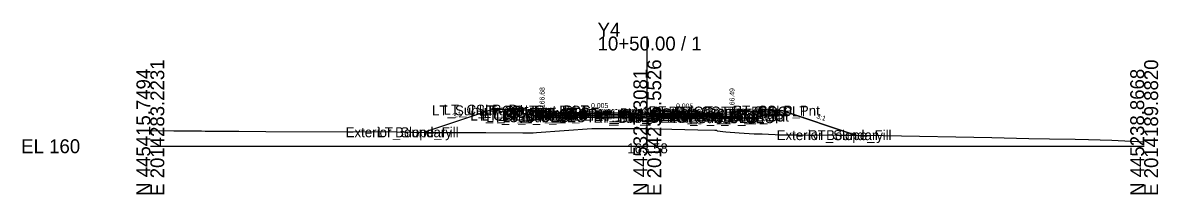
# Model space of a CAD drawing. Extents: x -26 to 203, y -10 to 4021.
# Drawn here: x -25.7 to 202.8, y 990.3 to 1024.9 of the extents above; entities that cross this region are included whole.
import ezdxf

# ---------------------------------------------------------------- set-up
doc = ezdxf.new("R2010")
doc.units = 0
for name, color, linetype in [('Default', 7, 'Continuous'), ('Exist Cross Section Cell', 7, 'Continuous'), ('Exist XS Center Line Elevation Label', 7, 'Continuous'), ('Exist XS Ground Line', 7, 'Continuous'), ('Prop CMT Conc Surface', 7, 'Continuous'), ('Prop CMT Concrete Structures', 7, 'Continuous'), ('Prop CMT Pvmt Course 1', 7, 'Continuous'), ('Prop CMT Pvmt Course 1 CG', 7, 'Continuous'), ('Prop CMT Pvmt Course 2', 7, 'Continuous'), ('Prop CMT Pvmt Course 3', 7, 'Continuous'), ('Prop CMT Pvmt Surface', 7, 'Continuous'), ('Prop CMT Slope Grass', 7, 'Continuous'), ('Prop CMT Subgrade Earthwork', 7, 'Continuous'), ('Prop XS Earthwork Shape', 7, 'Continuous'), ('Prop XS Hydro Elevations', 7, 'Continuous'), ('Prop XS SE Text', 7, 'Continuous'), ('Prop XS Side Slope Text', 7, 'Continuous'), ('Scratch_Level_0', 7, 'Continuous')]:
    doc.layers.add(name, color=color, linetype=linetype)

msp = doc.modelspace()

# ---------------------------------------------------------------- linework, layer by layer
at = {"layer": 'Exist Cross Section Cell'}
for p, q in [((100, 1000), (100, 1022.1)), ((0, 1000), (100, 1000)), ((100, 1000), (200, 1000))]:
    msp.add_line(p, q, dxfattribs=at)
at = {"layer": 'Exist XS Ground Line'}
msp.add_lwpolyline([(0, 1003.19), (4.69, 1003.1), (10.27, 1003.09), (11.05, 1003.06), (15.46, 1003.03), (17.82, 1003.04), (23.21, 1003), (41.56, 1002.89), (46.71, 1002.96), (55.46, 1002.8), (62.38, 1002.75), (67.52, 1002.77), (74.97, 1002.71), (77.03, 1002.69), (77.71, 1002.74), (88.86, 1003.57), (93.52, 1003.58), (99.73, 1003.59), (110.2, 1003.33), (113.59, 1003.22), (113.99, 1003.21), (114.05, 1003.09), (115.78, 1002.89), (118.52, 1002.67), (121.54, 1002.53), (121.94, 1002.51), (123.11, 1002.48), (126.99, 1002.27), (129.16, 1002.33), (130.4, 1002.3), (137.99, 1002.26), (140.42, 1002.26), (147.5, 1002.13), (151.18, 1002.07), (165.74, 1001.84), (169.37, 1001.76), (176.8, 1001.56), (180.95, 1001.49), (186.08, 1001.42), (188.79, 1001.38), (193.48, 1001.25), (200, 1000.87)], dxfattribs=at)
at = {"layer": 'Prop CMT Conc Surface'}
for points in [[(78.83, 1006.68), (78.83, 1007.18), (78.33, 1007.18)], [(80.83, 1006.75), (78.83, 1006.68)], [(115.05, 1006.58), (117.05, 1006.49)], [(117.05, 1006.49), (117.05, 1006.99), (117.55, 1006.99)]]:
    msp.add_lwpolyline(points, dxfattribs=at)
at = {"layer": 'Prop CMT Concrete Structures'}
for points in [[(80.83, 1006.75), (78.83, 1006.68), (78.83, 1007.18), (78.33, 1007.18)], [(78.33, 1007.18), (78.33, 1006.18), (80.83, 1006.16)], [(80.83, 1006.16), (80.83, 1006.75)], [(115.05, 1006.58), (117.05, 1006.49), (117.05, 1006.99), (117.55, 1006.99)], [(117.55, 1006.99), (117.55, 1005.98), (115.05, 1005.99)], [(115.05, 1005.99), (115.05, 1006.58)]]:
    msp.add_lwpolyline(points, dxfattribs=at)
at = {"layer": 'Prop CMT Pvmt Course 1'}
for points in [[(100, 1006.65), (80.83, 1006.75)], [(80.83, 1006.75), (80.83, 1006.5)], [(80.83, 1006.5), (100, 1006.4)], [(100, 1006.4), (100, 1006.65)], [(100, 1006.65), (115.05, 1006.58)], [(100, 1006.4), (100, 1006.65)], [(115.05, 1006.33), (100, 1006.4)], [(115.05, 1006.58), (115.05, 1006.33)]]:
    msp.add_lwpolyline(points, dxfattribs=at)
msp.add_lwpolyline([(100, 1006.4), (100, 1006.53), (100, 1006.53), (100, 1006.4)], close=True, dxfattribs=at)
msp.add_lwpolyline([(100, 1006.4), (100, 1006.53), (100, 1006.53), (100, 1006.4)], close=True, dxfattribs=at)
at = {"layer": 'Prop CMT Pvmt Course 1 CG'}
for points in [[(80.83, 1006.16), (77.83, 1006.18), (77.5, 1005.85)], [(77.5, 1005.85), (80.83, 1005.83)], [(80.83, 1005.83), (80.83, 1006.16)], [(115.05, 1005.99), (118.05, 1005.98), (118.38, 1005.64)], [(115.05, 1005.66), (115.05, 1005.99)], [(118.38, 1005.64), (115.05, 1005.66)]]:
    msp.add_lwpolyline(points, dxfattribs=at)
at = {"layer": 'Prop CMT Pvmt Course 2'}
for points in [[(100, 1006.4), (80.83, 1006.5)], [(80.83, 1006.5), (80.83, 1006.16)], [(80.83, 1006.16), (100, 1006.07)], [(100, 1006.07), (100, 1006.4)], [(100, 1006.07), (100, 1006.4)], [(100, 1006.4), (115.05, 1006.33)], [(115.05, 1005.99), (100, 1006.07)], [(115.05, 1006.33), (115.05, 1005.99)]]:
    msp.add_lwpolyline(points, dxfattribs=at)
at = {"layer": 'Prop CMT Pvmt Course 3'}
for points in [[(100, 1006.07), (80.83, 1006.16)], [(80.83, 1006.16), (80.83, 1005.83)], [(80.83, 1005.83), (100, 1005.73)], [(100, 1005.73), (100, 1006.07)], [(100, 1006.07), (115.05, 1005.99)], [(100, 1005.73), (100, 1006.07)], [(115.05, 1005.66), (100, 1005.73)], [(115.05, 1005.99), (115.05, 1005.66)]]:
    msp.add_lwpolyline(points, dxfattribs=at)
at = {"layer": 'Prop CMT Pvmt Surface'}
for points in [[(100, 1006.65), (80.83, 1006.75)], [(100, 1006.65), (115.05, 1006.58)]]:
    msp.add_lwpolyline(points, dxfattribs=at)
at = {"layer": 'Prop CMT Slope Grass'}
for points in [[(78.33, 1007.18), (68.83, 1007.37), (55.15, 1002.81)], [(117.55, 1006.99), (127.05, 1007.18), (141.89, 1002.23)]]:
    msp.add_lwpolyline(points, dxfattribs=at)
at = {"layer": 'Prop CMT Subgrade Earthwork'}
for points in [[(80.83, 1005.83), (77.5, 1005.85), (76.13, 1007.22)], [(100, 1005.73), (80.83, 1005.83)], [(100, 1005.73), (115.05, 1005.66)], [(115.05, 1005.66), (118.38, 1005.64), (119.77, 1007.03)]]:
    msp.add_lwpolyline(points, dxfattribs=at)
at = {"layer": 'Prop XS Earthwork Shape'}
msp.add_lwpolyline([(130.4, 1002.3), (137.99, 1002.26), (140.42, 1002.26), (141.89, 1002.23), (127.05, 1007.18), (119.77, 1007.03), (118.38, 1005.64), (115.05, 1005.66), (100, 1005.73), (80.83, 1005.83), (77.5, 1005.85), (76.13, 1007.22), (68.83, 1007.37), (55.15, 1002.81), (55.46, 1002.8), (62.38, 1002.75), (67.52, 1002.77), (74.97, 1002.71), (77.03, 1002.69), (77.71, 1002.74), (88.86, 1003.57), (93.52, 1003.58), (99.73, 1003.59), (110.2, 1003.33), (113.59, 1003.22), (113.99, 1003.21), (114.05, 1003.09), (115.78, 1002.89), (118.52, 1002.67), (121.54, 1002.53), (121.94, 1002.51), (123.11, 1002.48), (126.99, 1002.27), (129.16, 1002.33)], close=True, dxfattribs=at)

# ---------------------------------------------------------------- texts
at = {"layer": 'Default'}
msp.add_text('-', height=0.0001, dxfattribs=at).set_placement((0, 1000))
at = {"layer": 'Exist Cross Section Cell'}
for s, p in [('Y4', (90, 1022.1)), ('10+50.00 / 1', (90, 1019.3)), ('EL 160', (-26, 998.6))]:
    msp.add_text(s, height=2.8, dxfattribs=at).set_placement(p)
for s, p in [('E 2014283.2231', (2.8, 990)), ('E 2014236.5526', (102.8, 990)), ('E 2014189.8820', (202.8, 990)), ('N 445415.7494', (0, 990)), ('N 445327.3081', (100, 990)), ('N 445238.8668', (200, 990))]:
    msp.add_text(s, height=2.8, rotation=90, dxfattribs=at).set_placement(p)
at = {"layer": 'Exist XS Center Line Elevation Label'}
msp.add_text('163.58', height=2, dxfattribs=at).set_placement((95.96, 998.58))
at = {"layer": 'Prop XS Hydro Elevations'}
for s, p in [('166.68', (79.33, 1007.68)), ('166.49', (117.55, 1007.49))]:
    msp.add_text(s, height=1, rotation=90, dxfattribs=at).set_placement(p)
at = {"layer": 'Prop XS SE Text'}
for p in [(88.69, 1007.71), (105.79, 1007.62)]:
    msp.add_text('0.005', height=1, rotation=359.7135, dxfattribs=at).set_placement(p)
at = {"layer": 'Prop XS Side Slope Text'}
for rotation, p in [(18.4332, (61, 1005.55)), (341.5668, (133.95, 1005.67))]:
    msp.add_text('3:1', height=1, rotation=rotation, dxfattribs=at).set_placement(p)
at = {"layer": 'Scratch_Level_0'}
for s, p in [('LT_Sub_Trench_Out_DLT', (56.69, 1006.22)), ('LT_CSLP_Pnt', (59, 1006.37)), ('LT_CG_Top_Face', (66.09, 1006.18)), ('LT_CG_Top_BOC', (66.62, 1006.18)), ('RT_Sub_Trench_Out_DLT', (100.29, 1006.03)), ('RT_CG_Top_Face', (104.26, 1005.99)), ('RT_CG_Top_BOC', (105.78, 1005.99)), ('RT_CSLP_Pnt', (117.17, 1006.18)), ('LT_CG1_Shelf_Out', (64.38, 1005.18)), ('LT_CG_Bot_BOC', (66.65, 1005.18)), ('LT_CG_Top_Gut', (67.07, 1005.68)), ('LT_Sub_OEOP', (67.61, 1004.85)), ('LT_CG_Bot_IE', (70.75, 1005.16)), ('LT_Sub_OEOT', (70.91, 1004.83)), ('LT_PV2_OEOT', (71.01, 1005.5)), ('LT_PV3_OEOT', (71.01, 1005.16)), ('LT_PV1_OEOT', (71.57, 1005.75)), ('RT_Sub_OEEOP', (89.17, 1004.73)), ('LT_Sub_OEEOP', (89.21, 1004.73)), ('RT_PV2_OEEOP', (89.26, 1005.4)), ('RT_PV3_OEEOP', (89.26, 1005.07)), ('LT_PV2_OEEOP', (89.31, 1005.4)), ('LT_PV3_OEEOP', (89.31, 1005.07)), ('RT_PV1_OEEOP', (89.83, 1005.53)), ('LT_PV1_OEEOP', (89.87, 1005.53)), ('RT_PV2_IEEOP', (89.91, 1005.4)), ('LT_PV2_IEEOP', (89.95, 1005.4)), ('RT_PV1_IEEOP', (90.47, 1005.53)), ('LT_PV1_IEEOP', (90.52, 1005.53)), ('PV2_PGL', (93.91, 1005.4)), ('PV1_PGL', (94.47, 1005.65)), ('RT_CG1_Shelf_Out', (104.55, 1004.98)), ('RT_CG_Bot_IE', (104.91, 1004.99)), ('RT_Sub_OEOT', (105.08, 1004.66)), ('RT_PV2_OEOT', (105.17, 1005.33)), ('RT_PV3_OEOT', (105.17, 1004.99)), ('RT_CG_Top_Gut', (105.24, 1005.49)), ('RT_PV1_OEOT', (105.74, 1005.58)), ('RT_CG_Bot_BOC', (105.81, 1004.98)), ('RT_Sub_OEOP', (108.44, 1004.64)), ('Exterior Boundary', (39.29, 1001.81)), ('LT_Slope_Fill', (45.67, 1001.81)), ('Exterior Boundary', (126.03, 1001.23)), ('RT_Slope_Fill', (132.36, 1001.23))]:
    msp.add_text(s, height=2, dxfattribs=at).set_placement(p)

doc.saveas('drawing.dxf')
